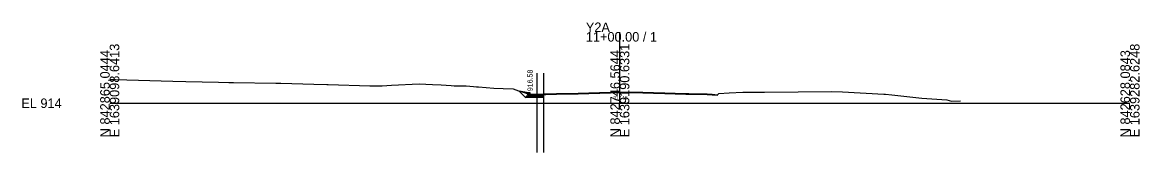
# Model space of a CAD drawing. Extents: x -26 to 303, y -10 to 10517.
# Drawn here: x -25.7 to 302.8, y 485.5 to 523.7 of the extents above; entities that cross this region are included whole.
import ezdxf

# ---------------------------------------------------------------- set-up
doc = ezdxf.new("R2010")
doc.units = 0
for name, color, linetype in [('Exist Cross Section Cell', 7, 'Continuous'), ('Exist XS Center Line Elevation Label', 7, 'Continuous'), ('Exist XS Ground Line', 7, 'Continuous'), ('Prop CMT Conc Surface', 7, 'Continuous'), ('Prop CMT Concrete Structures', 7, 'Continuous'), ('Prop CMT Pvmt Course 1', 7, 'Continuous'), ('Prop CMT Pvmt Course 1 CG', 7, 'Continuous'), ('Prop CMT Pvmt Course 2', 7, 'Continuous'), ('Prop CMT Pvmt Surface Overlay', 7, 'Continuous'), ('Prop CMT Slope Grass', 7, 'Continuous'), ('Prop CMT Subgrade Earthwork', 7, 'Continuous'), ('Prop XS Hydro Elevations', 7, 'Continuous'), ('Scratch_Level_0', 7, 'Continuous'), ('Scratch_Level_2', 7, 'Continuous')]:
    doc.layers.add(name, color=color, linetype=linetype)

msp = doc.modelspace()

# ---------------------------------------------------------------- linework, layer by layer
at = {"layer": 'Exist Cross Section Cell'}
for p, q in [((150, 500), (150, 520.9)), ((0, 500), (150, 500)), ((150, 500), (300, 500))]:
    msp.add_line(p, q, dxfattribs=at)
at = {"layer": 'Exist XS Ground Line'}
msp.add_lwpolyline([(0, 506.97), (1.23, 506.93), (1.74, 506.93), (11.81, 506.71), (15.12, 506.57), (18.53, 506.5), (22.34, 506.37), (31.95, 506.17), (35.07, 506.09), (36.42, 506.06), (48.86, 505.87), (49.2, 505.87), (49.59, 505.87), (49.98, 505.87), (50.33, 505.87), (60.03, 505.61), (63.79, 505.51), (64.19, 505.51), (76.47, 505.12), (78.22, 505.13), (80.06, 505.16), (82.81, 505.34), (90.96, 505.75), (94.87, 505.46), (97.48, 505.39), (100.35, 505.22), (101.32, 505.16), (104.85, 505.1), (106.95, 504.95), (107.8, 504.85), (108.43, 504.79), (112.95, 504.42), (115.7, 504.33), (118.59, 504.23), (120.22, 503.62), (121.52, 503.21), (122.7, 502.83), (123.13, 502.35), (123.63, 502.39), (125.12, 502.51), (126.55, 502.59), (127.5, 502.61), (128.24, 502.62), (130.62, 502.67), (131.41, 502.69), (132.85, 502.72), (134.67, 502.75), (136.04, 502.78), (137.74, 502.81), (138.19, 502.82), (138.78, 502.84), (140.9, 502.91), (142.85, 502.97), (144.07, 503.01), (145.32, 503.05), (147.23, 503.11), (148.88, 503.15), (150, 503.15), (150.66, 503.16), (151.01, 503.16), (153.56, 503.17), (155.62, 503.13), (156.73, 503.1), (157.79, 503.07), (159.16, 503.03), (159.57, 503.02), (159.89, 503.01), (162.44, 502.94), (163.24, 502.91), (166.22, 502.8), (166.86, 502.78), (167.86, 502.75), (169.39, 502.71), (170.26, 502.71), (171.39, 502.69), (172.55, 502.68), (175.68, 502.61), (176.57, 502.56), (177.17, 502.51), (178.64, 502.4), (179.09, 502.86), (182.11, 503.09), (186.14, 503.3), (186.82, 503.29), (192.54, 503.24), (202.43, 503.32), (212.33, 503.45), (215.47, 503.33), (227.61, 502.69), (228.13, 502.66), (229.93, 502.47), (238.8, 501.52), (246.18, 500.99), (247.54, 500.64), (250.14, 500.75)], dxfattribs=at)
at = {"layer": 'Prop CMT Conc Surface'}
msp.add_lwpolyline([(123.59, 502.58), (123.59, 503.08), (123.09, 503.08)], dxfattribs=at)
at = {"layer": 'Prop CMT Concrete Structures'}
for points in [[(125.59, 502.7), (123.59, 502.58), (123.59, 503.08), (123.09, 503.08)], [(123.09, 503.08), (123.09, 502.07), (125.59, 502.12)]]:
    msp.add_lwpolyline(points, dxfattribs=at)
at = {"layer": 'Prop CMT Pvmt Course 1'}
for p, q in [((125.59, 502.7), (127.59, 502.74)), ((125.59, 502.7), (125.59, 502.45)), ((127.59, 502.74), (127.59, 502.49)), ((125.59, 502.45), (127.59, 502.49))]:
    msp.add_line(p, q, dxfattribs=at)
at = {"layer": 'Prop CMT Pvmt Course 1 CG'}
for p, q in [((125.59, 502.12), (125.59, 501.79)), ((125.59, 501.79), (127.59, 501.83)), ((127.59, 502.16), (127.59, 501.83))]:
    msp.add_line(p, q, dxfattribs=at)
for points in [[(125.59, 502.12), (122.59, 502.06), (122.25, 501.72)], [(122.29, 501.72), (125.59, 501.79)]]:
    msp.add_lwpolyline(points, dxfattribs=at)
at = {"layer": 'Prop CMT Pvmt Course 2'}
for p, q in [((125.59, 502.12), (125.59, 502.45)), ((125.59, 502.12), (127.59, 502.16)), ((127.59, 502.16), (127.59, 502.49))]:
    msp.add_line(p, q, dxfattribs=at)
at = {"layer": 'Prop CMT Pvmt Surface Overlay'}
msp.add_lwpolyline([(127.59, 502.74), (128.24, 502.75), (130.62, 502.8), (131.4, 502.82), (132.84, 502.85), (134.67, 502.88), (136.04, 502.91), (137.74, 502.94), (138.19, 502.94), (138.77, 502.96), (140.9, 503.03), (142.85, 503.1), (144.06, 503.14), (145.31, 503.17), (147.23, 503.23), (148.88, 503.27), (150, 503.27), (150.66, 503.28), (151.01, 503.28), (153.56, 503.29), (155.62, 503.25), (156.73, 503.23), (157.79, 503.19), (159.16, 503.15), (159.58, 503.14), (159.9, 503.14), (162.45, 503.06), (163.24, 503.04), (166.23, 502.93), (166.86, 502.91), (167.86, 502.87), (169.39, 502.84), (170.26, 502.83), (171.39, 502.81), (172.56, 502.8), (175.68, 502.74), (176.58, 502.69), (177.18, 502.64), (178.76, 502.52)], dxfattribs=at)
at = {"layer": 'Prop CMT Slope Grass'}
msp.add_lwpolyline([(123.09, 503.08), (120.42, 503.56)], dxfattribs=at)
at = {"layer": 'Prop CMT Subgrade Earthwork'}
msp.add_lwpolyline([(125.59, 501.79), (122.25, 501.72), (120.42, 503.56)], dxfattribs=at)
at = {"layer": 'Scratch_Level_0'}
for p, q in [((125.59, 508.86), (125.59, 485.51)), ((127.59, 508.86), (127.59, 485.51))]:
    msp.add_line(p, q, dxfattribs=at)
at = {"layer": 'Scratch_Level_2'}
msp.add_line((127.59, 502.62), (127.5, 502.61), dxfattribs=at)
for points in [[(120.42, 503.56), (122.25, 501.72), (125.59, 501.79), (127.59, 501.83), (127.59, 502.62)], [(127.5, 502.61), (126.55, 502.59), (125.12, 502.51), (123.63, 502.39), (123.13, 502.35), (122.7, 502.83), (121.52, 503.21), (120.42, 503.56)], [(120.42, 503.56), (122.25, 501.72), (125.59, 501.79), (127.59, 501.83), (127.59, 502.62)]]:
    msp.add_lwpolyline(points, dxfattribs=at)

# ---------------------------------------------------------------- texts
at = {"layer": 'Exist Cross Section Cell'}
for s, p in [('Y2A', (140, 520.9)), ('11+00.00 / 1', (140, 518.1)), ('EL 914', (-26, 498.6))]:
    msp.add_text(s, height=2.8, dxfattribs=at).set_placement(p)
for s, p in [('E 1639098.6413', (2.8, 490)), ('E 1639190.6331', (152.8, 490)), ('E 1639282.6248', (302.8, 490)), ('N 842865.0444', (0, 490)), ('N 842746.5644', (150, 490)), ('N 842628.0843', (300, 490))]:
    msp.add_text(s, height=2.8, rotation=90, dxfattribs=at).set_placement(p)
at = {"layer": 'Exist XS Center Line Elevation Label'}
msp.add_text('917.15', height=1, dxfattribs=at).set_placement((148.1, 501.14))
at = {"layer": 'Prop XS Hydro Elevations'}
msp.add_text('916.58', height=1.5, rotation=90, dxfattribs=at).set_placement((124.34, 503.54))

doc.saveas('drawing.dxf')
